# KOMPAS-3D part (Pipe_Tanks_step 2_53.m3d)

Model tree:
1. X Axis
2. Y Axis
3. Z Axis  (labels: Pipe Dn 50)
     Òîëùèíà ñòåíêè 1 = 1

Referenced files in C:\Documents and Settings\kashirsky\Мои документы\Camtasia Studio\Pipelines3D\Tanks\: Tanks_step 2.a3d
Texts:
  Pipe Dn 50
  Steel ASTM A295
  Three Point Plane
  Plane at Angle
  Line and Point Plane
  Axis through Two Vertices
  Axis of Feature
  Axis of Conical Surface
  Axis through Edge
  Trim by Surface
  Trim by Sketch
  Feature with No History
  Intersection Axis of Two Planes
  Two Line Plane
  Line and Face Plane
  Bend by line
  Hole in sheet body
  Cut in sheet body
  Point in CM
  Linear Dimension from Line to Point
  Surface Finish Symbol
  Geometric Tolerance Symbol
  Leader #1
  Leader #2
  Leader #3
  Shape Deviations and Datum
  Node point number
  Mark of coordination axis
  Node point designation
  Mark/Reference designation with leader
  Mark/reference designation on line
  Mark/Reference designation without leader
  Plane of section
